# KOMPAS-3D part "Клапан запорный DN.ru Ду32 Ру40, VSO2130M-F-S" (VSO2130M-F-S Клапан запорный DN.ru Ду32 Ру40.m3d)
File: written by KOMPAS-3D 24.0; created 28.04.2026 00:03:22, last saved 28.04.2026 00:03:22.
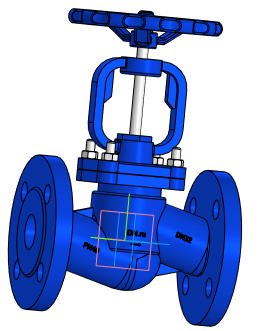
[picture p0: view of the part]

Document properties: Автор: DN.ru; Полное имя файла: C:\Работа\ГОТОВЫЕ ИСХОДНИКИ\VSO2130M-F-S Клапан запорный сальниковый DN.ru Ду15-100 Ру40\DN32\VSO2130M-F-S Клапан запорный DN.ru Ду32 Ру40.m3d

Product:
- Part/product: Клапан запорный DN.ru Ду32 Ру40  | designation VSO2130M-F-S
    Масса: 7.5
    Раздел спецификации: Прочие изделия
    Примечание: D090-01982

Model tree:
1. Операция без истории:1

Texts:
  VSO2130M-F-S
